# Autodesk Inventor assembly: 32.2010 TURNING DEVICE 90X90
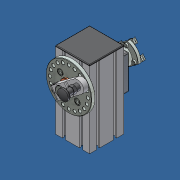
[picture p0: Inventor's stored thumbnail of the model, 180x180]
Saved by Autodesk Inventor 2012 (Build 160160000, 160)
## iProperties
Created: 2016-09
Part Number: 32.2010 TURNING DEVICE 90X90
Document SubType Name: Assembly
Designer: Admin
Author: Admin
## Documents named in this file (17)
- C:\Andys Backup Data\ANDY'S INVENTOR\INVENTOR LIBRARIES\PARTS LIBRARY\INDEXING POSITIONING AND FIXTURING\32.2010 TURNING DEVICE 90X90.iam
- C:\Andys Backup Data\ANDY'S INVENTOR\INVENTOR LIBRARIES\PARTS LIBRARY\INDEXING POSITIONING AND FIXTURING\SUBCOMPONENTS\32.2011 SLEEVE BEARING 25mm.ipt
- C:\Andys Backup Data\ANDY'S INVENTOR\INVENTOR LIBRARIES\PARTS LIBRARY\INDEXING POSITIONING AND FIXTURING\SUBCOMPONENTS\32.2011 90X90 MTG PLATE.ipt
- C:\Andys Backup Data\ANDY'S INVENTOR\INVENTOR LIBRARIES\PARTS LIBRARY\FASTENING ELEMENTS\SCREWS CAP\21.1202 M8X20.ipt
- C:\Andys Backup Data\ANDY'S INVENTOR\INVENTOR LIBRARIES\PARTS LIBRARY\FASTENING ELEMENTS\NUTS\21.1351_2 M8 SQUARE NUT POS FXG.ipt
- C:\Andys Backup Data\ANDY'S INVENTOR\INVENTOR LIBRARIES\PARTS LIBRARY\INDEXING POSITIONING AND FIXTURING\SUBCOMPONENTS\32.2011_FLANGE COUPLING 25.ipt
- C:\Andys Backup Data\ANDY'S INVENTOR\INVENTOR LIBRARIES\PARTS LIBRARY\INDEXING POSITIONING AND FIXTURING\SUBCOMPONENTS\32.2011 CIRCULAR DISK.ipt
- C:\Andys Backup Data\ANDY'S INVENTOR\INVENTOR LIBRARIES\PARTS LIBRARY\INDEXING POSITIONING AND FIXTURING\SUBCOMPONENTS\32.2010 25mm SHAFT.ipt
- C:\Andys Backup Data\ANDY'S INVENTOR\INVENTOR LIBRARIES\PARTS LIBRARY\FASTENING ELEMENTS\SCREWS CAP\21.1200 M8X16.ipt
- C:\Andys Backup Data\ANDY'S INVENTOR\INVENTOR LIBRARIES\PARTS LIBRARY\FASTENING ELEMENTS\NUTS\21.1330_2 M6 SQUARE NUT POS FXG.ipt
- C:\Andys Backup Data\ANDY'S INVENTOR\INVENTOR LIBRARIES\PARTS LIBRARY\INDEXING POSITIONING AND FIXTURING\SUBCOMPONENTS\32.2012 DETENT PIN M16X1.5.ipt
- C:\Andys Backup Data\ANDY'S INVENTOR\INVENTOR LIBRARIES\PARTS LIBRARY\INDEXING POSITIONING AND FIXTURING\SUBCOMPONENTS\32.2011 PLUNGER ARM.ipt
- C:\Andys Backup Data\ANDY'S INVENTOR\INVENTOR LIBRARIES\PARTS LIBRARY\FASTENING ELEMENTS\SCREWS CAP\21.1204 M8X25.ipt
- C:\Andys Backup Data\ANDY'S INVENTOR\INVENTOR LIBRARIES\PARTS LIBRARY\FASTENING ELEMENTS\SCREWS CAP\21.1222 M5X20.ipt
- C:\Andys Backup Data\ANDY'S INVENTOR\INVENTOR LIBRARIES\PARTS LIBRARY\INDEXING POSITIONING AND FIXTURING\SUBCOMPONENTS\32.2010 TURNING DEVICE 90X90 PROFILE 90S.ipt
- C:\Andys Backup Data\ANDY'S INVENTOR\INVENTOR LIBRARIES\PARTS LIBRARY\END CAPS\22.1069_1 END CAP 90X90 GRAY.ipt
- C:\Andys Backup Data\ANDY'S INVENTOR\INVENTOR LIBRARIES\PARTS LIBRARY\FASTENING ELEMENTS\SCREWS CAP\21.1240 M6X20.ipt
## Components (36 placed, 16 different names)
1. 32.2011 SLEEVE BEARING 25mm:2 — Insert:6, Mate:22, Mate:27
2. 32.2011 90X90 MTG PLATE:1 — Insert:2, Insert:3, Insert:4, Insert:5, Angle:1, Angle:2, Angle:3, Angle:4, Mate:6, Mate:7, Mate:8, Mate:9, Insert:6, Angle:6, Angle:7, Angle:8, Angle:9, Mate:42
3. 21.1202  M8 x 20:1 — Insert:2, Mate:1
4. 21.1202  M8 x 20:2 — Insert:5, Mate:2
5. 21.1202  M8 x 20:3 — Insert:3, Mate:3
6. 21.1202  M8 x 20:4 — Insert:4, Mate:4
7. 21.1351_2 M8 SQUARE NUT POS FXG:1 — Mate:2, Angle:1, Mate:8
8. 21.1351_2 M8 SQUARE NUT POS FXG:2 — Mate:3, Angle:4, Mate:7
9. 21.1351_2 M8 SQUARE NUT POS FXG:3 — Mate:1, Angle:2, Mate:9
10. 21.1351_2 M8 SQUARE NUT POS FXG:4 — Mate:4, Angle:3, Mate:6
11. 32.2011_FLANGE COUPLING 25:1 — Mate:22, Insert:12, Insert:13, Insert:14, Insert:15, Angle:10, Angle:11, Angle:12, Angle:13, Insert:16, Insert:17, Insert:18, Insert:19, Insert:21, Mate:27, Angle:14, Mate:43
12. 32.2010 25mm SHAFT:1 — Mate:24, Flush:1, Mate:40, Mate:43
13. 21.1200 M8 x 16:1 — Mate:15, Insert:25
14. 21.1200 M8 x 16:2 — Mate:14, Insert:24
15. 21.1200 M8 x 16:3 — Mate:16, Insert:26
16. 21.1200 M8 x 16:4 — Mate:17, Mate:36, Mate:37
17. 21.1351_2 M8 SQUARE NUT POS FXG:5 — Mate:15, Angle:6, Angle:15, Mate:38
18. 21.1351_2 M8 SQUARE NUT POS FXG:6 — Mate:14, Angle:7, Mate:34
19. 21.1351_2 M8 SQUARE NUT POS FXG:7 — Mate:16, Angle:8, Mate:39, Angle:16
20. 21.1351_2 M8 SQUARE NUT POS FXG:8 — Mate:17, Angle:9, Mate:35
21. 21.1330_2 M6 SQUARE NUT POS FXG:1 — Insert:12, Angle:11
22. 21.1330_2 M6 SQUARE NUT POS FXG:2 — Insert:13, Angle:10
23. 21.1330_2 M6 SQUARE NUT POS FXG:3 — Insert:14, Angle:12
24. 21.1330_2 M6 SQUARE NUT POS FXG:4 — Insert:15, Angle:13
25. 21.1240  M6x20 SHCS:1 — Insert:16
26. 21.1240  M6x20 SHCS:2 — Insert:17
27. 21.1240  M6x20 SHCS:3 — Insert:18
28. 21.1240  M6x20 SHCS:4 — Insert:19
29. 32.2012 DETENT PIN M16X1.5:1 — Mate:25, Mate:26
30. 32.2011 PLUNGER ARM:1 — Insert:20, Mate:24, Mate:25, Mate:26, Flush:1, Angle:14, Mate:41
31. 21.1204  M8 x 25:1 — Insert:20
32. 21.1222 M5 x 20:1 — Insert:21
33. 32.2010 TURNING DEVICE 90X90 PROFILE 90S:1 — Mate:31, Mate:32, Mate:33, Mate:34, Mate:35, Angle:15, Mate:38, Mate:39, Angle:16, Mate:42, Insert:27, Angle:17
34. 32.2011 CIRCULAR DISK:2 — Mate:31, Mate:32, Mate:33, Insert:23, Insert:24, Mate:36, Mate:37, Insert:25, Insert:26
35. 32.2011 SLEEVE BEARING 25mm:3 — Insert:23, Mate:40, Mate:41
36. 22.1069_1 END CAP 90X90 GRAY:1 — Insert:27, Angle:17
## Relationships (67: Mate 30, Insert 20, Angle 16, Flush 1)
- Insert:2: 32.2011 90X90 MTG PLATE:1 ↔ 21.1202  M8 x 20:1
- Insert:3: 32.2011 90X90 MTG PLATE:1 ↔ 21.1202  M8 x 20:3
- Insert:4: 32.2011 90X90 MTG PLATE:1 ↔ 21.1202  M8 x 20:4
- Insert:5: 32.2011 90X90 MTG PLATE:1 ↔ 21.1202  M8 x 20:2
- Mate:1: 21.1202  M8 x 20:1 ↔ 21.1351_2 M8 SQUARE NUT POS FXG:3
- Mate:2: 21.1202  M8 x 20:2 ↔ 21.1351_2 M8 SQUARE NUT POS FXG:1
- Mate:3: 21.1202  M8 x 20:3 ↔ 21.1351_2 M8 SQUARE NUT POS FXG:2
- Mate:4: 21.1202  M8 x 20:4 ↔ 21.1351_2 M8 SQUARE NUT POS FXG:4
- Angle:1: 32.2011 90X90 MTG PLATE:1 ↔ 21.1351_2 M8 SQUARE NUT POS FXG:1
- Angle:2: 32.2011 90X90 MTG PLATE:1 ↔ 21.1351_2 M8 SQUARE NUT POS FXG:3
- Angle:3: 32.2011 90X90 MTG PLATE:1 ↔ 21.1351_2 M8 SQUARE NUT POS FXG:4
- Angle:4: 32.2011 90X90 MTG PLATE:1 ↔ 21.1351_2 M8 SQUARE NUT POS FXG:2
- Mate:6: 32.2011 90X90 MTG PLATE:1 ↔ 21.1351_2 M8 SQUARE NUT POS FXG:4
- Mate:7: 32.2011 90X90 MTG PLATE:1 ↔ 21.1351_2 M8 SQUARE NUT POS FXG:2
- Mate:8: 32.2011 90X90 MTG PLATE:1 ↔ 21.1351_2 M8 SQUARE NUT POS FXG:1
- Mate:9: 32.2011 90X90 MTG PLATE:1 ↔ 21.1351_2 M8 SQUARE NUT POS FXG:3
- Insert:6: 32.2011 SLEEVE BEARING 25mm:2 ↔ 32.2011 90X90 MTG PLATE:1
- Mate:14: 21.1200 M8 x 16:2 ↔ 21.1351_2 M8 SQUARE NUT POS FXG:6
- Mate:15: 21.1200 M8 x 16:1 ↔ 21.1351_2 M8 SQUARE NUT POS FXG:5
- Mate:16: 21.1200 M8 x 16:3 ↔ 21.1351_2 M8 SQUARE NUT POS FXG:7
- Mate:17: 21.1200 M8 x 16:4 ↔ 21.1351_2 M8 SQUARE NUT POS FXG:8
- Angle:6: 32.2011 90X90 MTG PLATE:1 ↔ 21.1351_2 M8 SQUARE NUT POS FXG:5
- Angle:7: 32.2011 90X90 MTG PLATE:1 ↔ 21.1351_2 M8 SQUARE NUT POS FXG:6
- Angle:8: 32.2011 90X90 MTG PLATE:1 ↔ 21.1351_2 M8 SQUARE NUT POS FXG:7
- Angle:9: 32.2011 90X90 MTG PLATE:1 ↔ 21.1351_2 M8 SQUARE NUT POS FXG:8
- Mate:22: 32.2011 SLEEVE BEARING 25mm:2 ↔ 32.2011_FLANGE COUPLING 25:1
- Insert:12: 32.2011_FLANGE COUPLING 25:1 ↔ 21.1330_2 M6 SQUARE NUT POS FXG:1
- Insert:13: 32.2011_FLANGE COUPLING 25:1 ↔ 21.1330_2 M6 SQUARE NUT POS FXG:2
- Insert:14: 32.2011_FLANGE COUPLING 25:1 ↔ 21.1330_2 M6 SQUARE NUT POS FXG:3
- Insert:15: 32.2011_FLANGE COUPLING 25:1 ↔ 21.1330_2 M6 SQUARE NUT POS FXG:4
- Angle:10: 32.2011_FLANGE COUPLING 25:1 ↔ 21.1330_2 M6 SQUARE NUT POS FXG:2
- Angle:11: 32.2011_FLANGE COUPLING 25:1 ↔ 21.1330_2 M6 SQUARE NUT POS FXG:1
- Angle:12: 32.2011_FLANGE COUPLING 25:1 ↔ 21.1330_2 M6 SQUARE NUT POS FXG:3
- Angle:13: 32.2011_FLANGE COUPLING 25:1 ↔ 21.1330_2 M6 SQUARE NUT POS FXG:4
- Insert:16: 32.2011_FLANGE COUPLING 25:1 ↔ 21.1240  M6x20 SHCS:1
- Insert:17: 32.2011_FLANGE COUPLING 25:1 ↔ 21.1240  M6x20 SHCS:2
- Insert:18: 32.2011_FLANGE COUPLING 25:1 ↔ 21.1240  M6x20 SHCS:3
- Insert:19: 32.2011_FLANGE COUPLING 25:1 ↔ 21.1240  M6x20 SHCS:4
- Insert:20: 32.2011 PLUNGER ARM:1 ↔ 21.1204  M8 x 25:1
- Mate:24: 32.2010 25mm SHAFT:1 ↔ 32.2011 PLUNGER ARM:1
- Insert:21: 32.2011_FLANGE COUPLING 25:1 ↔ 21.1222 M5 x 20:1
- Mate:25: 32.2012 DETENT PIN M16X1.5:1 ↔ 32.2011 PLUNGER ARM:1
- Mate:26: 32.2012 DETENT PIN M16X1.5:1 ↔ 32.2011 PLUNGER ARM:1
- Flush:1: 32.2010 25mm SHAFT:1 ↔ 32.2011 PLUNGER ARM:1
- Mate:27: 32.2011 SLEEVE BEARING 25mm:2 ↔ 32.2011_FLANGE COUPLING 25:1
- Angle:14: 32.2011_FLANGE COUPLING 25:1 ↔ 32.2011 PLUNGER ARM:1
- Mate:31: 32.2010 TURNING DEVICE 90X90 PROFILE 90S:1 ↔ 32.2011 CIRCULAR DISK:2
- Mate:32: 32.2010 TURNING DEVICE 90X90 PROFILE 90S:1 ↔ 32.2011 CIRCULAR DISK:2
- Mate:33: 32.2010 TURNING DEVICE 90X90 PROFILE 90S:1 ↔ 32.2011 CIRCULAR DISK:2
- Insert:23: 32.2011 CIRCULAR DISK:2 ↔ 32.2011 SLEEVE BEARING 25mm:3
- Mate:34: 21.1351_2 M8 SQUARE NUT POS FXG:6 ↔ 32.2010 TURNING DEVICE 90X90 PROFILE 90S:1
- Insert:24: 21.1200 M8 x 16:2 ↔ 32.2011 CIRCULAR DISK:2
- Mate:35: 21.1351_2 M8 SQUARE NUT POS FXG:8 ↔ 32.2010 TURNING DEVICE 90X90 PROFILE 90S:1
- Mate:36: 21.1200 M8 x 16:4 ↔ 32.2011 CIRCULAR DISK:2
- Mate:37: 21.1200 M8 x 16:4 ↔ 32.2011 CIRCULAR DISK:2
- Angle:15: 21.1351_2 M8 SQUARE NUT POS FXG:5 ↔ 32.2010 TURNING DEVICE 90X90 PROFILE 90S:1
- Mate:38: 21.1351_2 M8 SQUARE NUT POS FXG:5 ↔ 32.2010 TURNING DEVICE 90X90 PROFILE 90S:1
- Insert:25: 21.1200 M8 x 16:1 ↔ 32.2011 CIRCULAR DISK:2
- Mate:39: 21.1351_2 M8 SQUARE NUT POS FXG:7 ↔ 32.2010 TURNING DEVICE 90X90 PROFILE 90S:1
- Angle:16: 21.1351_2 M8 SQUARE NUT POS FXG:7 ↔ 32.2010 TURNING DEVICE 90X90 PROFILE 90S:1
- Insert:26: 21.1200 M8 x 16:3 ↔ 32.2011 CIRCULAR DISK:2
- Mate:40: 32.2010 25mm SHAFT:1 ↔ 32.2011 SLEEVE BEARING 25mm:3
- Mate:41: 32.2011 PLUNGER ARM:1 ↔ 32.2011 SLEEVE BEARING 25mm:3
- Mate:42: 32.2011 90X90 MTG PLATE:1 ↔ 32.2010 TURNING DEVICE 90X90 PROFILE 90S:1
- Mate:43: 32.2011_FLANGE COUPLING 25:1 ↔ 32.2010 25mm SHAFT:1
- Insert:27: 32.2010 TURNING DEVICE 90X90 PROFILE 90S:1 ↔ 22.1069_1 END CAP 90X90 GRAY:1
- Angle:17: 32.2010 TURNING DEVICE 90X90 PROFILE 90S:1 ↔ 22.1069_1 END CAP 90X90 GRAY:1
